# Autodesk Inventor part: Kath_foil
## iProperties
Shininess: 64.0
Length Units: 11269
Angle Units: 11279
Time Units: 11290
Mass Units: 11283
Length Display Precision: 3
Angle Display Precision: 2
Compacted: True
Part Number: Kath_foil
Document SubType Name: Modeling
Created: 2003-02
Material: Standard
Designer: hofer_a
Density: 0.0
Volumn: 0.0
Area: 0.0
PropertySet Name: Model Information
Control State: 0
Master: False
Checked Out: False
Author: hofer_a
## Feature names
1. Extrusion1
2. Bohrung1 [Hole]
3. Bohrung2 [Hole]
